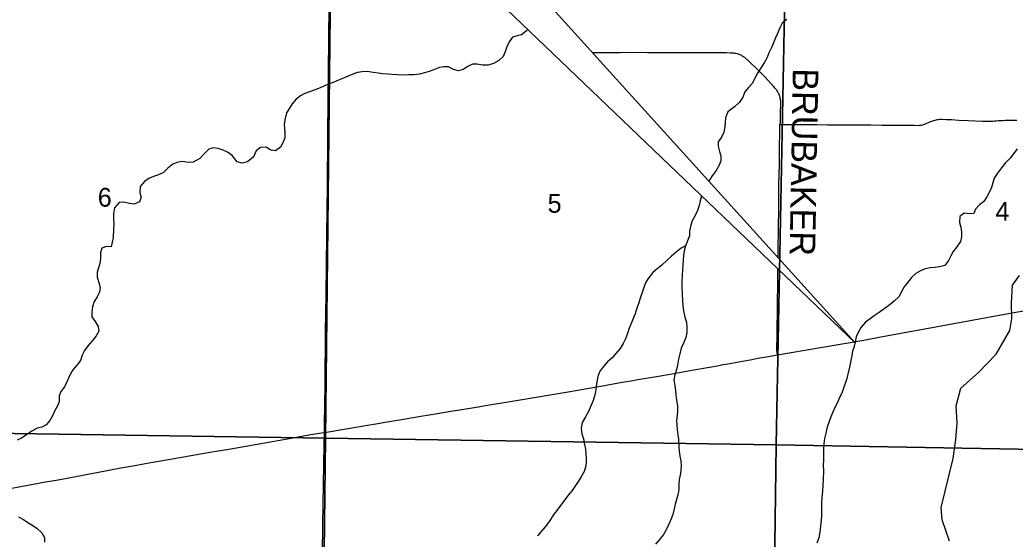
# Model space of a CAD drawing. Extents: x 0 to 34, y 0 to 22.
# Drawn here: x 27.199 to 28.307, y 14.655 to 15.233 of the extents above; entities that cross this region are included whole.
import ezdxf

# ---------------------------------------------------------------- set-up
doc = ezdxf.new("R2010")
doc.units = 0
for name, color, linetype in [('GM_X_County_Road', 7, 'Continuous'), ('GM_X_Minor_River', 7, 'Continuous'), ('GM_X_Section', 7, 'Continuous'), ('GM_X_Section_Text', 7, 'Continuous'), ('GM_X_State_Route', 7, 'Continuous'), ('GM_X_Township_Road', 7, 'Continuous'), ('GM_X_Township_Road_Text', 7, 'Continuous'), ('SH_Text', 7, 'Continuous')]:
    doc.layers.add(name, color=color, linetype=linetype)

msp = doc.modelspace()

# ---------------------------------------------------------------- linework, layer by layer
at = {"layer": 'GM_X_County_Road'}
for points in [[(27.5384, 14.7738), (27.5384, 14.7744), (27.5383, 14.7825), (27.539, 14.8269), (27.5397, 14.8859), (27.5402, 14.9263), (27.5411, 14.9937), (27.5417, 15.0487), (27.5421, 15.1028), (27.5426, 15.1456), (27.543, 15.1745), (27.5433, 15.213), (27.5436, 15.249), (27.544, 15.2823), (27.5439, 15.2888), (27.5437, 15.2922), (27.5433, 15.2947), (27.5429, 15.2969), (27.5423, 15.2987), (27.5414, 15.3011), (27.5402, 15.3035), (27.5394, 15.3051), (27.5386, 15.3064), (27.5376, 15.3077)], [(27.5358, 14.607), (27.5366, 14.6704), (27.537, 14.6937), (27.5381, 14.7595), (27.5384, 14.7738)]]:
    msp.add_lwpolyline(points, dxfattribs=at)
at = {"layer": 'GM_X_Minor_River'}
for points in [[(28.0529, 15.2337), (28.0479, 15.2296), (28.045, 15.2243), (28.0424, 15.2181), (28.0404, 15.2132), (28.038, 15.2076), (28.0357, 15.2023), (28.0329, 15.1965), (28.0311, 15.1912), (28.0278, 15.1854), (28.0235, 15.1789), (28.0203, 15.174), (28.0178, 15.1689), (28.0146, 15.1629), (28.0104, 15.1579), (28.0063, 15.153), (28.0041, 15.1472), (28.0004, 15.1416), (27.9948, 15.1364), (27.9871, 15.1308), (27.9845, 15.124), (27.9844, 15.1191), (27.9841, 15.114), (27.9827, 15.108), (27.9801, 15.1025), (27.9766, 15.0973), (27.9767, 15.0925), (27.9779, 15.0866), (27.9796, 15.0817), (27.9793, 15.0764), (27.9775, 15.0715), (27.9743, 15.0656), (27.97, 15.0595), (27.9663, 15.0537), (27.9662, 15.0535)], [(27.7647, 15.2226), (27.763, 15.2207), (27.7576, 15.2166), (27.7527, 15.2156), (27.7475, 15.2138), (27.7438, 15.2089), (27.7414, 15.2033), (27.7396, 15.1978), (27.7374, 15.1925), (27.7324, 15.1881), (27.7265, 15.1848), (27.7204, 15.1826), (27.7141, 15.1827), (27.7084, 15.184), (27.7033, 15.1839), (27.6978, 15.1813), (27.6926, 15.1778), (27.6876, 15.1766), (27.6821, 15.1778), (27.6763, 15.181), (27.6712, 15.1811), (27.6664, 15.18), (27.6607, 15.178), (27.6548, 15.1759), (27.6498, 15.1741), (27.6441, 15.1726), (27.6382, 15.172), (27.6321, 15.1721), (27.6261, 15.1718), (27.6198, 15.172), (27.6139, 15.1725), (27.6088, 15.1729), (27.6035, 15.1732), (27.598, 15.1739), (27.5927, 15.1747), (27.5861, 15.1756), (27.5804, 15.1753), (27.5751, 15.1747), (27.5701, 15.1729), (27.5649, 15.1705), (27.5594, 15.1682), (27.5539, 15.166), (27.5479, 15.1636), (27.5424, 15.1616), (27.5368, 15.1591)], [(27.5368, 15.1591), (27.5317, 15.1567), (27.5269, 15.1549), (27.5219, 15.1531), (27.5166, 15.1511), (27.5118, 15.1487), (27.5068, 15.1449), (27.5025, 15.1398), (27.4994, 15.1349), (27.4963, 15.1297), (27.4945, 15.1235), (27.4936, 15.1172), (27.4939, 15.1119), (27.4943, 15.107), (27.4944, 15.102), (27.4926, 15.0972), (27.4893, 15.0915), (27.4839, 15.0875), (27.4786, 15.0881), (27.4734, 15.0913), (27.4673, 15.091), (27.4625, 15.0873), (27.4593, 15.0807), (27.4526, 15.0751), (27.4467, 15.0735), (27.4414, 15.0752), (27.4358, 15.0823), (27.4306, 15.086), (27.4257, 15.0882), (27.4202, 15.0898), (27.4145, 15.0906), (27.4096, 15.0892), (27.4047, 15.0842), (27.3997, 15.079), (27.3921, 15.0747), (27.3867, 15.0745), (27.3803, 15.0755), (27.3752, 15.0749), (27.3696, 15.0725), (27.3642, 15.0681), (27.3594, 15.0632), (27.3537, 15.0605), (27.3483, 15.0589), (27.343, 15.0565), (27.3382, 15.0532), (27.3333, 15.0476), (27.3328, 15.0406), (27.3344, 15.0358), (27.3324, 15.0305), (27.3265, 15.028), (27.3216, 15.0288), (27.315, 15.0303), (27.31, 15.03), (27.3046, 15.0238), (27.3035, 15.0172), (27.3036, 15.0121), (27.3041, 15.0058), (27.3038, 15.0002), (27.3032, 14.9907), (27.3022, 14.9858), (27.301, 14.9803), (27.2957, 14.9808), (27.2905, 14.9788), (27.2893, 14.9737), (27.2891, 14.9674), (27.2885, 14.962), (27.2871, 14.9571), (27.2855, 14.9522), (27.2855, 14.9467), (27.2873, 14.9407), (27.2887, 14.935), (27.2881, 14.9299), (27.2853, 14.9247), (27.2822, 14.9196), (27.2802, 14.9138), (27.2795, 14.9081), (27.2794, 14.9026), (27.2831, 14.8972), (27.2864, 14.8919), (27.2873, 14.8867), (27.2845, 14.8815), (27.2806, 14.8766), (27.2756, 14.8706), (27.2715, 14.8652), (27.2688, 14.86), (27.2668, 14.8539), (27.2633, 14.8489), (27.2584, 14.8436), (27.2553, 14.8384), (27.2515, 14.8303), (27.249, 14.8245), (27.2451, 14.8194), (27.2433, 14.8142), (27.243, 14.8079), (27.2408, 14.8026), (27.238, 14.7974), (27.2357, 14.7923), (27.2329, 14.7871), (27.2288, 14.7822), (27.224, 14.7798), (27.2187, 14.7784)], [(28.3091, 15.0897), (28.3053, 15.0839), (28.3015, 15.0791), (28.296, 15.0735), (28.2918, 15.0684), (28.2873, 15.0626), (28.2838, 15.0568), (28.282, 15.0519), (28.2806, 15.0467), (28.2786, 15.0416), (28.2756, 15.0361), (28.2723, 15.0311), (28.2675, 15.0274), (28.263, 15.0225), (28.2609, 15.0176), (28.2557, 15.0172), (28.2503, 15.0178), (28.2453, 15.0141), (28.2449, 15.0077), (28.2466, 15.0024), (28.2474, 14.9967), (28.2473, 14.9917), (28.2461, 14.9863), (28.2422, 14.9804), (28.2381, 14.9752), (28.2355, 14.9703), (28.233, 14.9651), (28.2287, 14.9597), (28.223, 14.9581), (28.218, 14.9576), (28.2125, 14.9569), (28.2068, 14.9559), (28.2016, 14.9539), (28.1965, 14.9506), (28.1915, 14.9465), (28.1878, 14.9416), (28.1835, 14.9358), (28.1807, 14.9308), (28.1778, 14.9253), (28.1722, 14.9199), (28.1664, 14.9151), (28.1612, 14.9114), (28.1558, 14.9075), (28.1503, 14.9037), (28.1455, 14.9002), (28.1404, 14.8965), (28.1356, 14.891), (28.1327, 14.8858), (28.1301, 14.8802), (28.1289, 14.8745), (28.1278, 14.8694), (28.126, 14.8641), (28.1252, 14.8592), (28.1241, 14.8537), (28.1226, 14.8465), (28.121, 14.8388), (28.1198, 14.8337), (28.1179, 14.8281), (28.116, 14.823), (28.114, 14.8175), (28.1116, 14.8126), (28.1092, 14.8072), (28.1068, 14.8021), (28.1041, 14.7963), (28.1019, 14.791), (28.0979, 14.7797), (28.0962, 14.7729), (28.0948, 14.7671), (28.0941, 14.7612), (28.0938, 14.7547), (28.0937, 14.7489), (28.0938, 14.7432), (28.0935, 14.7369), (28.0936, 14.7314), (28.0934, 14.7204), (28.0931, 14.715), (28.0926, 14.7083), (28.0917, 14.7017), (28.0914, 14.6953), (28.0915, 14.6901), (28.0915, 14.6814), (28.0912, 14.6759), (28.0897, 14.6627), (28.0884, 14.6563), (28.0862, 14.6506)], [(27.9581, 15.0372), (27.9564, 15.0318), (27.9552, 15.0264), (27.9534, 15.0209), (27.9508, 15.0155), (27.9477, 15.0096), (27.9461, 15.0045), (27.9448, 14.9981), (27.9445, 14.9926), (27.9423, 14.987), (27.9402, 14.9815), (27.9387, 14.9759), (27.9381, 14.9708), (27.9376, 14.9656), (27.9371, 14.9602), (27.9368, 14.9547), (27.9365, 14.9488), (27.936, 14.9414), (27.9359, 14.9363), (27.9365, 14.9272), (27.9368, 14.9211), (27.9372, 14.9147), (27.9381, 14.9093), (27.9395, 14.9023), (27.9411, 14.8964), (27.9417, 14.8909), (27.9416, 14.8848), (27.9406, 14.8795), (27.938, 14.8731), (27.9352, 14.8675), (27.9338, 14.8614), (27.9325, 14.8552), (27.9313, 14.8488), (27.9302, 14.8437), (27.9284, 14.838), (27.9273, 14.8318), (27.9282, 14.8259), (27.929, 14.8204), (27.9295, 14.8156), (27.9303, 14.8096), (27.9312, 14.8033), (27.9313, 14.7978), (27.931, 14.7929)], [(27.9402, 14.9815), (27.9352, 14.9788), (27.9296, 14.9747), (27.9246, 14.9701), (27.9197, 14.9656), (27.9138, 14.96), (27.9088, 14.9559), (27.9039, 14.9517), (27.8985, 14.9453), (27.8958, 14.9405), (27.8938, 14.935), (27.892, 14.9295), (27.8898, 14.9233), (27.8881, 14.918), (27.8861, 14.912), (27.8841, 14.9058), (27.8776, 14.89), (27.8756, 14.884), (27.8734, 14.8779), (27.8708, 14.8729), (27.8673, 14.8674), (27.8628, 14.8618), (27.8584, 14.857), (27.8534, 14.8525), (27.8489, 14.8473), (27.845, 14.8419), (27.8426, 14.8362), (27.8416, 14.83), (27.8409, 14.8249), (27.84, 14.819), (27.839, 14.8141), (27.8374, 14.8092), (27.8342, 14.8015), (27.832, 14.7964), (27.8287, 14.791), (27.8252, 14.7848), (27.8241, 14.7784), (27.8249, 14.7723), (27.8265, 14.7668), (27.8277, 14.7603), (27.8288, 14.755), (27.8293, 14.7498), (27.8295, 14.7447), (27.8297, 14.74), (27.8288, 14.735), (27.8274, 14.7301), (27.8246, 14.7251), (27.8211, 14.7196), (27.8176, 14.7148), (27.8139, 14.7092), (27.8096, 14.7039), (27.8057, 14.6987), (27.8021, 14.6938), (27.798, 14.6884), (27.7941, 14.683), (27.7876, 14.6736), (27.7839, 14.6686), (27.7797, 14.6634), (27.7754, 14.6585)], [(28.2341, 14.6525), (28.2259, 14.6764), (28.2245, 14.6903), (28.238, 14.7448), (28.241, 14.7658), (28.2424, 14.7844), (28.2412, 14.8035), (28.2466, 14.8229), (28.2661, 14.8407), (28.286, 14.8611), (28.301, 14.8874), (28.3035, 14.9006), (28.3028, 14.9176), (28.3042, 14.9379), (28.3118, 14.9486)], [(27.931, 14.7929), (27.9303, 14.7868), (27.9304, 14.7821), (27.9309, 14.7771), (27.9315, 14.7712), (27.9322, 14.7661), (27.9328, 14.7578), (27.9331, 14.753), (27.9338, 14.7473), (27.9348, 14.742), (27.9354, 14.7361), (27.9347, 14.728), (27.9333, 14.7212), (27.9328, 14.7162), (27.9327, 14.7102), (27.9318, 14.7043), (27.93, 14.699), (27.9288, 14.6937), (27.9274, 14.6887), (27.9259, 14.6824), (27.9241, 14.6775), (27.9215, 14.6715), (27.9188, 14.6653), (27.9156, 14.6601), (27.9116, 14.655), (27.9067, 14.6494)], [(27.2187, 14.7784), (27.2129, 14.7751), (27.2072, 14.7714), (27.2012, 14.7675), (27.1963, 14.765)], [(27.1979, 14.6796), (27.2034, 14.6769), (27.2082, 14.6736), (27.2139, 14.6701), (27.2187, 14.6666), (27.224, 14.6619), (27.2269, 14.6567), (27.227, 14.6514)]]:
    msp.add_lwpolyline(points, dxfattribs=at)
at = {"layer": 'GM_X_Section'}
for points in [[(27.0476, 15.3154), (27.5327, 15.3085), (27.5456, 15.308), (27.5395, 14.7672), (27.0444, 14.7747)], [(27.5456, 15.308), (28.0326, 15.3013), (28.0515, 15.301), (28.0411, 14.7598), (27.5395, 14.7672)], [(28.0515, 15.301), (28.5416, 15.294), (28.5381, 14.7512), (28.0411, 14.7598)], [(27.5395, 14.7672), (27.5335, 14.2635), (27.036, 14.27), (27.0444, 14.7747)], [(28.0411, 14.7598), (28.0345, 14.2582), (27.5335, 14.2635), (27.5395, 14.7672)], [(28.5381, 14.7512), (28.5357, 14.2494), (28.0345, 14.2582), (28.0411, 14.7598)]]:
    msp.add_lwpolyline(points, close=True, dxfattribs=at)
at = {"layer": 'GM_X_State_Route'}
msp.add_lwpolyline([(27.1823, 14.7104), (27.2064, 14.7147), (27.2279, 14.7186), (27.2419, 14.721), (27.252, 14.7228), (27.2752, 14.7272), (27.2868, 14.7294), (27.3118, 14.7342), (27.325, 14.7367), (27.3353, 14.7386), (27.3473, 14.7406), (27.3672, 14.744), (27.373, 14.745), (27.3773, 14.7458), (27.388, 14.7477), (27.4131, 14.752), (27.418, 14.7528), (27.4251, 14.754), (27.4321, 14.7553), (27.4532, 14.759), (27.4801, 14.7638), (27.4973, 14.7668), (27.5211, 14.771), (27.5377, 14.7737), (27.5384, 14.7738), (27.5472, 14.7752), (27.5558, 14.7767), (27.5711, 14.7794), (27.5839, 14.7816), (27.5977, 14.7839), (27.6081, 14.7856), (27.6262, 14.7887), (27.6458, 14.7919), (27.6642, 14.7949), (27.6792, 14.7973), (27.6912, 14.7994), (27.7071, 14.802), (27.7261, 14.8052), (27.7384, 14.8072), (27.7629, 14.8111), (27.7829, 14.8144), (27.8074, 14.8186), (27.8202, 14.8208), (27.8306, 14.8226), (27.8459, 14.8254), (27.8698, 14.8297), (27.8796, 14.8314), (27.8872, 14.8327), (27.9102, 14.8366), (27.923, 14.8388), (27.9313, 14.8402), (27.9392, 14.8416), (27.9515, 14.8437), (27.9601, 14.8452), (27.9757, 14.848), (27.9802, 14.8489), (27.9894, 14.8506), (27.9973, 14.8521), (28.012, 14.8547), (28.0172, 14.8556), (28.023, 14.8567), (28.0251, 14.8571), (28.0303, 14.858), (28.0362, 14.8591), (28.0425, 14.8602), (28.0903, 14.8684), (28.1386, 14.8767), (28.1594, 14.8805), (28.2025, 14.8884), (28.2568, 14.8984), (28.2974, 14.9057), (28.3354, 14.9124)], dxfattribs=at)
at = {"layer": 'GM_X_Township_Road'}
for points in [[(27.8365, 15.197), (27.8467, 15.197), (27.8673, 15.197), (27.874, 15.1971), (27.8979, 15.197), (27.9336, 15.1969), (27.9635, 15.1969), (27.9774, 15.1969), (27.9815, 15.1969), (27.9858, 15.1968), (27.9902, 15.1967), (27.9919, 15.1966), (27.9935, 15.1964), (27.9948, 15.1962), (27.9961, 15.196), (27.9975, 15.1956), (27.9986, 15.1953), (27.9994, 15.1951), (28.0004, 15.1947), (28.0014, 15.1943), (28.0024, 15.1938), (28.0032, 15.1933), (28.0043, 15.1926), (28.0057, 15.1916), (28.0071, 15.1904), (28.0105, 15.1873), (28.013, 15.185), (28.0179, 15.1803), (28.0237, 15.1746), (28.0262, 15.172), (28.0288, 15.1693), (28.038, 15.1592), (28.039, 15.158), (28.0402, 15.1566), (28.041, 15.1556), (28.0416, 15.1548), (28.042, 15.154), (28.0426, 15.1532), (28.0432, 15.1522), (28.0436, 15.1513), (28.0439, 15.1505), (28.0444, 15.1493), (28.0449, 15.1481), (28.0451, 15.1469), (28.0453, 15.1459), (28.0455, 15.145), (28.0456, 15.1442), (28.0457, 15.1432), (28.0458, 15.1415), (28.0457, 15.1386), (28.0456, 15.1308), (28.0455, 15.1268), (28.0454, 15.1202), (28.0453, 15.1167)], [(28.0453, 15.1167), (28.0487, 15.1167), (28.054, 15.1167), (28.0645, 15.1167), (28.0748, 15.1166), (28.0862, 15.1166), (28.0982, 15.1165), (28.1105, 15.1164), (28.1261, 15.1163), (28.1463, 15.1162), (28.1592, 15.1161), (28.1696, 15.116), (28.1787, 15.1159), (28.189, 15.1158), (28.1949, 15.1158), (28.1994, 15.1157), (28.2007, 15.1158), (28.2019, 15.1158), (28.2027, 15.1159), (28.2039, 15.1162), (28.2051, 15.1166), (28.2071, 15.1174), (28.2121, 15.1195), (28.2142, 15.1203), (28.2164, 15.1211), (28.2179, 15.1216), (28.2192, 15.122), (28.2203, 15.1222), (28.2215, 15.1224), (28.2229, 15.1225), (28.2242, 15.1226), (28.2259, 15.1226), (28.2302, 15.1224), (28.2367, 15.1221), (28.2442, 15.1217), (28.2547, 15.1213), (28.2708, 15.1206), (28.2729, 15.1206), (28.275, 15.1205), (28.2768, 15.1205), (28.2785, 15.1205), (28.2823, 15.1206), (28.2841, 15.1207), (28.2858, 15.1208), (28.2886, 15.121), (28.2916, 15.1212), (28.2935, 15.1213), (28.2958, 15.1214), (28.2975, 15.1215), (28.3003, 15.1215), (28.3026, 15.1216), (28.3088, 15.1217)], [(28.0432, 14.9683), (28.0432, 14.9687), (28.0433, 14.9756), (28.0434, 14.9834), (28.0436, 14.9947), (28.0437, 15.0081), (28.0439, 15.017), (28.044, 15.0292), (28.0441, 15.0386), (28.0442, 15.044), (28.0442, 15.05), (28.0444, 15.0613), (28.0446, 15.0721), (28.0447, 15.0793), (28.0449, 15.0961), (28.045, 15.1027), (28.0451, 15.1073), (28.0453, 15.1107), (28.0453, 15.1167)], [(28.0425, 14.8602), (28.042, 14.8628), (28.042, 14.8636), (28.0419, 14.8648), (28.0419, 14.8664), (28.0419, 14.8708), (28.042, 14.8773), (28.0421, 14.8853), (28.0423, 14.8956), (28.0425, 14.903), (28.0426, 14.9144), (28.0427, 14.9229), (28.0428, 14.934), (28.0431, 14.9557)]]:
    msp.add_lwpolyline(points, dxfattribs=at)
at = {"layer": 'SH_Text'}
msp.add_lwpolyline([(27.448, 15.8284), (25.5147, 15.8284), (25.5147, 15.4253), (27.448, 15.4253), (27.448, 15.526), (28.1289, 14.8734), (27.448, 15.6268)], close=True, dxfattribs=at)

# ---------------------------------------------------------------- texts
at = {"layer": 'GM_X_Section_Text'}
for s, p in [('6', (27.2861, 15.0252)), ('5', (27.7867, 15.0184)), ('4', (28.2851, 15.0095))]:
    msp.add_text(s, height=0.0209, rotation=0, dxfattribs=at).set_placement(p)
at = {"layer": 'GM_X_Township_Road_Text'}
msp.add_text('BRUBAKER', height=0.02841, rotation=268.9905, dxfattribs=at).set_placement((28.0597, 15.1795))

doc.saveas('drawing.dxf')
